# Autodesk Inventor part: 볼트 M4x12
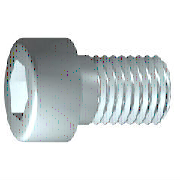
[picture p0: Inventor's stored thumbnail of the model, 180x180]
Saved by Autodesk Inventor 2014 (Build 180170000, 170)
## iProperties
IsCustomPart: 0
Created: 2012-02
Part Number: 볼트 M4x12
Material: 강철, 연강
Description: 6각 소켓 머리 캡 나사
Document SubType Name: Modeling
Standard: ISO 4762
Designer: mduedu
Standard Revision: Fourth edition 2004-03-01
Standards Organization: ISO
Language: ko-KR
Size Designation: M4 x 12
Categories: <MemberInstance><Categories><Category DisplayName="조임쇠" InternalName="e4da775c-781d-43d5-af7c-5136215cf5a6" Mnemonic="FSTN"><Category DisplayName="볼트" InternalN
Density: 7.75 g/cm^3
Appearance: Steel
Author: mduedu
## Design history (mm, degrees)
sketch "스케치1"
  geometry: L1 (-1, 0)-(12, 0); L2 (12, 0)-(12, 2); L3 (12, 2)-(1.75, 2); L4 (1.75, 2)-(1.32, 2); L5 (1.32, 2)-(0, 2); L6 (0, 2)-(0, 3.5); L7 (0, 3.5)-(-4, 3.5); L8 (-4, 3.5)-(-4, 1.732); L9 (-4, 1.732)-(-2, 1.732); L10 (-2, 1.732)-(-1, 0); L11 (-7.2, 0)-(15.2, 0) reference; L12 (0, -0.7)-(0, 4.2) reference; L13 (1.75, 2)-(0, 2)
  constraints: 22 end point, 6 parallel, 2 collinear, 2 perpendicular, 1 horizontal, 1 point on line
  dimensions: "d1" = 10.25 distance from line of L3.end L2 (= GEL); "d2" = 0.42952 distance of L4.end L3.end (computed from GAL); "d3" = 4 distance between parallel lines of L8 L6 (= KOH); "d4" = 2 distance of L8.end L9.end (= INTI); "d5" = 60 deg angle of L10 L1; "d6" = 4 diameter of L3 L1 (= GD); "d7" = 4 diameter of L5 L1 (= BDM); "d8" = 3.4641 diameter of L9 L1 (= 1.1547 x SW); "d9" = 7 diameter of L7 L1 (= KOD); "d26" = 12 distance between parallel lines of L12 L2 (= NLG)
revolve "본체" sketch "스케치1" stored, may be unused: angle "d10" = 90 deg
sketch "스케치2"
  geometry: L1 (0, -4.9)-(0, 4.9) reference; L2 (-4.9, 0)-(4.9, 0) reference; L3 (1.732, 0)-(0.866, -1.5); L4 (0.866, -1.5)-(-0.866, -1.5); L5 (-0.866, -1.5)-(-1.732, 0); L6 (-1.732, 0)-(-0.866, 1.5); L7 (-0.866, 1.5)-(0.866, 1.5); L8 (0.866, 1.5)-(1.732, 0); 2 further points
  constraints: 12 end point, 1 coincident, 1 horizontal alignment, 1 point on line, 12 other
extrude "슬롯" join sketch "스케치2" stored distance "d11" = 10; taper "d12" = 0 deg
workplane "Work Plane1"
fillet "Fillet2" dims "d30" = 0.1 (= R)
body "Solid1"
fillet "모깎기1" dims "d17" = 0.4 (= RR)
feature "스레드" dims "d13" = 10.25 (= GEL), "d14" = 0
chamfer "모따기1" distance "d15" = 0.42941 (= -0.5 x SPD + 0.5 x GD); stored, may be unused: second distance "d16" = 0.42941 (= GUL), angle "d27" = 45 deg
other parameters: "GD" = 4 [user parameter; used in 2 equation terms], "NLG" = 12 [user parameter; used in 1 equation term], "GEL" = 10.25 [user parameter; used in 2 equation terms], "KOD" = 7 [user parameter; used in 1 equation term], "KOH" = 4 [user parameter; used in 1 equation term], "INTI" = 2 [user parameter; used in 1 equation term], "GAL" = 0.42941 (= 0.61345 x PTC) [user parameter; used in 1 equation term], "GUL" = 0.42941 (= 0.61345 x PTC) [user parameter; used in 1 equation term], "BDM" = 4 (= NND) [user parameter; used in 1 equation term], "SW" = 3 [user parameter; used in 2 equation terms], "RR" = 0.4 [user parameter; used in 1 equation term], "SPD" = 3.14117 (= NND - 1.2269 x PTC) [user parameter; used in 1 equation term], "d19" = 0, "d28" = 0, "d29" = 0, "R" = 0.1 [user parameter; used in 1 equation term], "TOA" = 30 deg [user parameter], "GD1" = 3.14117 (= THREADDIA - 1.2269 x PTC) [user parameter], "THREADDIA" = 4 [user parameter; used in 1 equation term], "FAWI" = 45 deg [user parameter], "TPU" = 14.28571 (computed from PTC) [user parameter], "PTC" = 0.7 [user parameter; used in 5 equation terms], "NND" = 4 [user parameter; used in 2 equation terms], "E0" = 3.465 (= 1.155 x SW) [user parameter]
